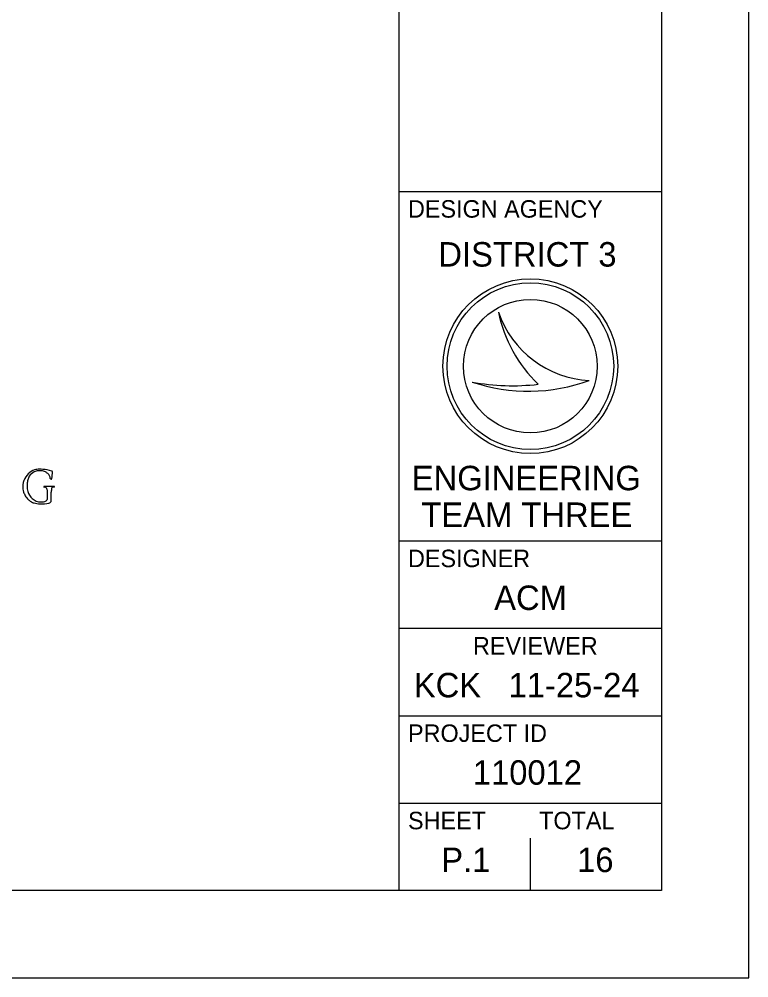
# Model space of a CAD drawing. Extents: x 0 to 34, y 0 to 22.
# Drawn here: x 29.83 to 34, y 0 to 5.49 of the extents above; entities that cross this region are included whole.
import ezdxf

# ---------------------------------------------------------------- set-up
doc = ezdxf.new("R2010")
doc.units = 0
for name, color, linetype in [('SH_Border', 7, 'Continuous'), ('SH_Cut_Line', 7, 'Continuous'), ('SH_Data', 7, 'Continuous'), ('SH_Text', 7, 'Continuous')]:
    doc.layers.add(name, color=color, linetype=linetype)

msp = doc.modelspace()

# ---------------------------------------------------------------- linework, layer by layer
at = {"layer": 'SH_Border'}
for p, q in [((32, 0.5), (32, 21.5)), ((32, 4.5), (33.5, 4.5)), ((32, 2.5), (33.5, 2.5)), ((32, 2), (33.5, 2)), ((32, 1.5), (33.5, 1.5)), ((32, 1), (33.5, 1))]:
    msp.add_line(p, q, dxfattribs=at)
msp.add_lwpolyline([(1.5, 21.5), (33.5, 21.5), (33.5, 0.5), (1.5, 0.5)], close=True, dxfattribs=at)
at = {"layer": 'SH_Cut_Line'}
msp.add_lwpolyline([(0, 0), (34, 0), (34, 22), (0, 22)], close=True, dxfattribs=at)
at = {"layer": 'SH_Data'}
for p, q in [((32.5674, 3.8096), (32.5675, 3.8096)), ((32.75, 3.5), (32.75, 3.5)), ((32.4172, 3.4095), (32.4172, 3.4095)), ((33.0873, 3.4185), (33.0873, 3.4185)), ((32.75, 0.5), (32.75, 0.8)), ((32.375, 0.675), (32.375, 0.675))]:
    msp.add_line(p, q, dxfattribs=at)
for radius in [0.5, 0.4768, 0.4768, 0.3822]:
    msp.add_circle((32.75, 3.5), radius, dxfattribs=at)
for centre, radius, start, end in [((33.1159, 3.9976), 0.5798, 198.9257, 198.9319), ((33.3467, 3.9701), 0.7956, 191.6379, 191.6421), ((33.1159, 3.9976), 0.5798, 198.9319, 267.1657), ((33.3467, 3.9701), 0.7956, 191.6421, 226.0947), ((32.7394, 4.37), 1.0131, 251.4576, 290.0832), ((32.648, 4.6543), 1.2661, 259.4964, 259.4995), ((32.7394, 4.37), 1.0131, 251.4527, 251.4576), ((32.648, 4.6543), 1.2661, 259.4995, 276.6672)]:
    msp.add_arc(centre, radius, start, end, dxfattribs=at)
at = {"layer": 'SH_Text'}
for p, q in [((30.0259, 2.8118), (29.9684, 2.8118)), ((29.9852, 2.7932), (29.9852, 2.7371)), ((30.0088, 2.7316), (30.0088, 2.7792))]:
    msp.add_line(p, q, dxfattribs=at)
for centre, radius, start, end in [((29.9406, 2.8189), 0.0916, 90.0889, 107.613), ((29.9408, 2.6564), 0.254, 85.6243, 90.0889), ((29.9417, 2.6672), 0.2432, 73.3259, 85.6243), ((29.9598, 2.803), 0.1159, 135.2994, 157.2066), ((29.9433, 2.8315), 0.0714, 147.5385, 165.5071), ((29.9391, 2.8235), 0.0867, 107.613, 135.2994), ((29.9433, 2.8315), 0.0714, 116.7026, 147.5385), ((29.9377, 2.8427), 0.0589, 93.5922, 116.7026), ((29.9448, 2.7297), 0.1722, 87.6816, 93.5922), ((29.9497, 2.8509), 0.0509, 59.809, 87.6816), ((29.9164, 2.7936), 0.1171, 52.0865, 59.809), ((29.9648, 2.8557), 0.0384, 2.9119, 52.0865), ((30.0076, 2.8579), 0.00447, 182.9119, 350.1479), ((30.01, 2.8955), 0.00494, 1.0594, 73.3259), ((29.8123, 2.8918), 0.2027, 350.1479, 1.0594), ((29.937, 2.8079), 0.0913, 176.8679, 187.4835), ((29.9863, 2.8052), 0.1407, 167.8164, 176.8679), ((29.9158, 2.8204), 0.0685, 158.442, 167.8164), ((29.9598, 2.803), 0.1159, 157.2066, 158.442), ((30.0122, 2.8152), 0.1422, 167.8795, 178.2857), ((29.9679, 2.8165), 0.0979, 178.2857, 190.5998), ((30.1026, 2.8417), 0.2349, 190.5998, 194.5022), ((29.979, 2.8223), 0.1082, 165.5071, 167.8795), ((29.9684, 2.8097), 0.00203, 90, 277.32), ((29.9705, 2.7932), 0.0146, 0, 97.32), ((30.1677, 2.7792), 0.1589, 172.0456, 180), ((30.0161, 2.8004), 0.00585, 114.8736, 172.0456), ((30.0238, 2.7837), 0.0242, 95.8947, 114.8736), ((30.0392, 2.6347), 0.174, 94.3316, 95.8947), ((30.0259, 2.81), 0.00179, 274.3316, 90), ((29.9248, 2.8063), 0.0789, 187.4835, 199.5864), ((29.9922, 2.8303), 0.1505, 199.5864, 208.6065), ((29.9316, 2.7972), 0.0815, 208.6065, 229.3453), ((29.9543, 2.8034), 0.0818, 194.5022, 227.8932), ((29.9534, 2.8226), 0.1149, 229.3453, 237.7571), ((29.9286, 2.7834), 0.0686, 237.7571, 254.2366), ((29.9501, 2.7987), 0.0755, 227.8932, 268.7516), ((29.9465, 2.8466), 0.1343, 254.2366, 269.1033), ((29.9492, 3.0179), 0.3056, 269.1033, 278.6618), ((29.9501, 2.7982), 0.075, 268.7516, 293.6665), ((29.9769, 2.7371), 0.00829, 293.6665, 0), ((29.9928, 2.7316), 0.016, 278.6618, 0)]:
    msp.add_arc(centre, radius, start, end, dxfattribs=at)

# ---------------------------------------------------------------- texts
at = {"layer": 'SH_Data'}
for s, height, p in [('DESIGN AGENCY', 0.1, (32.05, 4.35)), ('DISTRICT 3', 0.14, (32.2237, 4.07)), ('ENGINEERING', 0.14, (32.0713, 2.79)), ('TEAM THREE', 0.14, (32.1266, 2.58)), ('DESIGNER', 0.1, (32.05, 2.35)), ('ACM', 0.14, (32.5431, 2.105)), ('REVIEWER', 0.1, (32.4218, 1.85)), ('KCK', 0.14, (32.0833, 1.605)), ('11-25-24', 0.14, (32.6254, 1.605)), ('PROJECT ID', 0.1, (32.05, 1.35)), ('110012', 0.14, (32.4209, 1.105)), ('SHEET', 0.1, (32.05, 0.85)), ('TOTAL', 0.1, (32.8, 0.85)), ('P.1', 0.14, (32.2403, 0.605)), ('16', 0.14, (33.0176, 0.605))]:
    msp.add_text(s, height=height, dxfattribs=at).set_placement(p)

doc.saveas('drawing.dxf')
